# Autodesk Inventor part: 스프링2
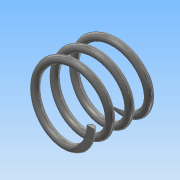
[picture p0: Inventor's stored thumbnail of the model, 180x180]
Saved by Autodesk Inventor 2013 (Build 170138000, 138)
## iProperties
Created: 2016-10
Part Number: 스프링2
Material: 강철, 탄소
Document SubType Name: Modeling
Designer: Administrator
Mass: 6.66824 g
Surface Area: 17.432 cm^2
Volume: 0.847298 cm^3
Density: 7.87 g/cm^3
Author: Administrator
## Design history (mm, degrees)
sketch "스케치1"
  geometry: L1 (0, 0)-(0, 26); L2 (0, 26)-(25, 26); C1 r 1 at (9, 0)
  constraints: 4 end point, 1 centre point, 1 horizontal alignment, 1 perpendicular, 1 vertical
  dimensions: "d0" = 26 distance of L1.start L1.end (derived); "d1" = 25 distance of L1.end L2.end; "d2" = 2 diameter of C1; "d3" = 18 diameter of C1.centre L1
feature "코일1" sketch "스케치1" pitch "d4" = 10; turns "d6" = 5; dims "d5" = 27, "d7" = 0, angle "d8" = 90 deg, angle "d9" = 90 deg, "d10" = 0, "d11" = 0
sketch "스케치2"
  geometry: L1 (26, 12)-(0, 12); L2 (0, 12)-(0, -12); L3 (0, -12)-(26, -12); L4 (26, -12)-(26, 12); 2 further points
  constraints: 8 end point, 2 parallel, 1 coincident, 1 horizontal, 1 midpoint, 1 perpendicular
  dimensions: "d12" = 26 distance of L1.start L1.end (derived); "d14" = 24 distance of L3.end L1.start
extrude "돌출1" sketch "스케치2" stored distance "d15" = 0; taper "d16" = 0 deg
node "솔리드1"
